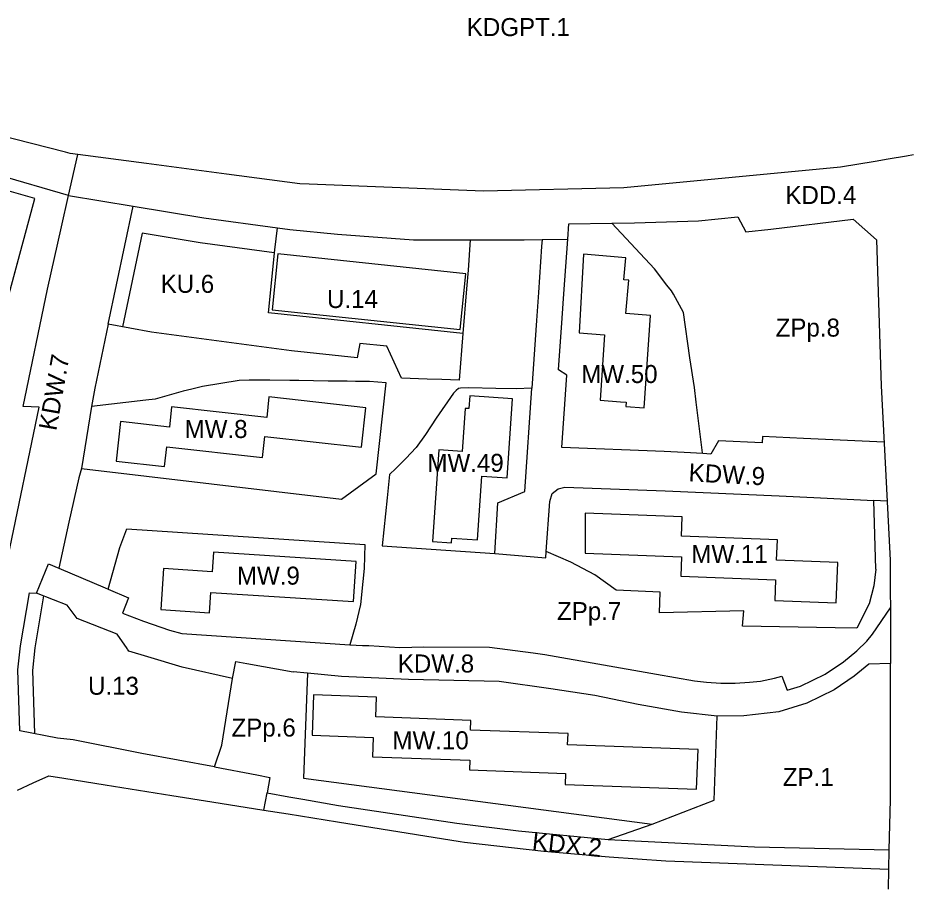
# Model space of a CAD drawing. Extents: x 7424434 to 7425898, y 5541432 to 5542659.
# Drawn here: x 7425170.3 to 7425417.1, y 5542089.1 to 5542330.8 of the extents above; entities that cross this region are included whole.
import ezdxf

# ---------------------------------------------------------------- set-up
doc = ezdxf.new("R2010")
doc.units = 0
for name, color, linetype in [('linie rozgraniczające', 7, 'Continuous'), ('nieprzekraczalne linie zabudowy', 7, 'Continuous'), ('obowiazujace linie zabudowy', 7, 'Continuous'), ('przeznaczenia terenów', 7, 'Continuous')]:
    doc.layers.add(name, color=color, linetype=linetype)

msp = doc.modelspace()

# ---------------------------------------------------------------- linework, layer by layer
at = {"layer": 'linie rozgraniczające'}
for p, q in [((7425183.57, 5542293.49), (7425160.74, 5542299.31)), ((7425184.89, 5542293.16), (7425183.57, 5542293.49)), ((7425187.01, 5542292.88), (7425184.89, 5542293.16)), ((7425184.45, 5542281.48), (7425148.18, 5542291.98)), ((7425184.45, 5542281.48), (7425187.01, 5542292.88)), ((7425206.02, 5542290.37), (7425187.01, 5542292.88)), ((7425408.2, 5542290.96), (7425398.58, 5542289.34)), ((7425411.81, 5542291.57), (7425408.2, 5542290.96)), ((7425416.94, 5542292.44), (7425411.81, 5542291.57)), ((7425418.88, 5542292.83), (7425416.94, 5542292.44)), ((7425175.09, 5542280.69), (7425147.13, 5542288.57)), ((7425228.29, 5542287.44), (7425206.02, 5542290.37)), ((7425398.58, 5542289.34), (7425338.51, 5542283.67)), ((7425248.56, 5542284.77), (7425228.29, 5542287.44)), ((7425251.22, 5542284.67), (7425248.56, 5542284.77)), ((7425299.51, 5542282.71), (7425251.22, 5542284.67)), ((7425338.51, 5542283.67), (7425299.51, 5542282.71)), ((7425162.36, 5542233.68), (7425175.09, 5542280.69)), ((7425182.51, 5542272.81), (7425184.45, 5542281.48)), ((7425184.45, 5542281.48), (7425202.31, 5542278.54)), ((7425195.46, 5542245.86), (7425202.31, 5542278.54)), ((7425202.31, 5542278.54), (7425221.99, 5542275.3)), ((7425221.99, 5542275.3), (7425242.43, 5542272.51)), ((7425322.91, 5542269.36), (7425323.21, 5542273.68)), ((7425323.21, 5542273.68), (7425335.12, 5542273.85)), ((7425335.12, 5542273.85), (7425341.48, 5542273.94)), ((7425346.97, 5542261.14), (7425335.12, 5542273.85)), ((7425341.48, 5542273.94), (7425359.22, 5542274.44)), ((7425359.22, 5542274.44), (7425370.12, 5542275.56)), ((7425370.12, 5542275.56), (7425372.37, 5542271.39)), ((7425379.27, 5542272.2), (7425402.12, 5542274.91)), ((7425402.12, 5542274.91), (7425408.57, 5542269.23)), ((7425178.62, 5542255.49), (7425182.51, 5542272.81)), ((7425241.69, 5542266.47), (7425242.43, 5542272.51)), ((7425242.43, 5542272.51), (7425245.84, 5542272.04)), ((7425245.84, 5542272.04), (7425259.08, 5542270.79)), ((7425259.08, 5542270.79), (7425280.15, 5542269.21)), ((7425372.37, 5542271.39), (7425379.27, 5542272.2)), ((7425280.15, 5542269.21), (7425295.81, 5542269.18)), ((7425295.81, 5542269.18), (7425295.25, 5542260.76)), ((7425295.81, 5542269.18), (7425310.79, 5542269.21)), ((7425310.79, 5542269.21), (7425315.8, 5542269.31)), ((7425315.8, 5542269.31), (7425315.67, 5542267.36)), ((7425315.8, 5542269.31), (7425322.91, 5542269.36)), ((7425321.86, 5542254.22), (7425322.91, 5542269.36)), ((7425408.57, 5542269.23), (7425409.91, 5542228.71)), ((7425239.87, 5542248.96), (7425241.69, 5542266.47)), ((7425315.67, 5542267.36), (7425314.8, 5542254.6)), ((7425350.41, 5542256.68), (7425346.97, 5542261.14)), ((7425295.25, 5542260.76), (7425294.84, 5542255.66)), ((7425351.68, 5542255.1), (7425350.41, 5542256.68)), ((7425171.81, 5542223), (7425178.62, 5542255.49)), ((7425294.84, 5542255.66), (7425293.83, 5542243.21)), ((7425314.8, 5542254.6), (7425314.27, 5542246.83)), ((7425321.4, 5542247.51), (7425321.86, 5542254.22)), ((7425352.22, 5542254.19), (7425351.68, 5542255.1)), ((7425355.05, 5542249.09), (7425352.22, 5542254.19)), ((7425293.83, 5542243.21), (7425239.87, 5542248.96)), ((7425356.82, 5542236.48), (7425355.05, 5542249.09)), ((7425314.27, 5542246.83), (7425313, 5542228.06)), ((7425320.35, 5542233.2), (7425321.4, 5542247.51)), ((7425195.46, 5542245.86), (7425191.73, 5542228.05)), ((7425207.44, 5542243.57), (7425195.46, 5542245.86)), ((7425246.3, 5542238.39), (7425207.44, 5542243.57)), ((7425293.83, 5542243.21), (7425292.77, 5542230.26)), ((7425265.25, 5542240.49), (7425264.54, 5542236.45)), ((7425272.74, 5542239.73), (7425265.25, 5542240.49)), ((7425276.84, 5542230.88), (7425272.74, 5542239.73)), ((7425264.54, 5542236.45), (7425246.3, 5542238.39)), ((7425358.08, 5542228.28), (7425356.82, 5542236.48)), ((7425322.66, 5542231.64), (7425320.35, 5542233.2)), ((7425321.3, 5542211.63), (7425322.66, 5542231.64)), ((7425231.73, 5542230.19), (7425221.58, 5542228.53)), ((7425234.56, 5542230.26), (7425231.73, 5542230.19)), ((7425240.3, 5542230.31), (7425234.56, 5542230.26)), ((7425245.85, 5542230.22), (7425240.3, 5542230.31)), ((7425248.36, 5542230.23), (7425245.85, 5542230.22)), ((7425256.47, 5542230.02), (7425248.36, 5542230.23)), ((7425260.5, 5542229.98), (7425256.47, 5542230.02)), ((7425261.68, 5542229.97), (7425260.5, 5542229.98)), ((7425264, 5542229.95), (7425261.68, 5542229.97)), ((7425267.93, 5542229.89), (7425264, 5542229.95)), ((7425272.56, 5542229.57), (7425267.93, 5542229.89)), ((7425269.75, 5542204.28), (7425272.56, 5542229.57)), ((7425283.94, 5542230.6), (7425276.84, 5542230.88)), ((7425288.03, 5542230.44), (7425283.94, 5542230.6)), ((7425292.77, 5542230.26), (7425288.03, 5542230.44)), ((7425191.73, 5542228.05), (7425190.81, 5542222.98)), ((7425216.2, 5542227.23), (7425208.46, 5542225.01)), ((7425218.66, 5542227.75), (7425216.2, 5542227.23)), ((7425221.58, 5542228.53), (7425218.66, 5542227.75)), ((7425291.22, 5542226.72), (7425286.45, 5542219.76)), ((7425291.93, 5542227.41), (7425291.22, 5542226.72)), ((7425292.61, 5542227.94), (7425291.93, 5542227.41)), ((7425293.16, 5542228.08), (7425292.61, 5542227.94)), ((7425295.47, 5542228.13), (7425293.16, 5542228.08)), ((7425302.93, 5542228.02), (7425295.47, 5542228.13)), ((7425308.61, 5542227.85), (7425302.93, 5542228.02)), ((7425313, 5542228.06), (7425308.61, 5542227.85)), ((7425311.05, 5542199.37), (7425313, 5542228.06)), ((7425358.59, 5542224.18), (7425358.08, 5542228.28)), ((7425409.91, 5542228.71), (7425410.74, 5542212.77)), ((7425205.89, 5542224.7), (7425190.81, 5542222.98)), ((7425208.46, 5542225.01), (7425205.89, 5542224.7)), ((7425360.33, 5542210.18), (7425358.59, 5542224.18)), ((7425167.64, 5542181.41), (7425176.32, 5542222.8)), ((7425176.32, 5542222.8), (7425171.81, 5542223)), ((7425190.81, 5542222.98), (7425188, 5542205.78)), ((7425286.45, 5542219.76), (7425283.44, 5542215.23)), ((7425283.44, 5542215.23), (7425280.85, 5542211.58)), ((7425376.96, 5542214.66), (7425376.86, 5542212.91)), ((7425388.36, 5542214.11), (7425376.96, 5542214.66)), ((7425410.72, 5542213.06), (7425388.36, 5542214.11)), ((7425280.85, 5542211.58), (7425278.01, 5542208.52)), ((7425349.63, 5542210.5), (7425321.3, 5542211.63)), ((7425364.71, 5542213.43), (7425362.61, 5542209.79)), ((7425376.86, 5542212.91), (7425364.71, 5542213.43)), ((7425410.74, 5542212.77), (7425411.12, 5542205.58)), ((7425355.24, 5542210.2), (7425349.63, 5542210.5)), ((7425360.36, 5542209.92), (7425355.24, 5542210.2)), ((7425360.36, 5542209.92), (7425360.33, 5542210.18)), ((7425362.61, 5542209.79), (7425360.36, 5542209.92)), ((7425278.01, 5542208.52), (7425275.19, 5542205.77)), ((7425188, 5542205.78), (7425187.26, 5542203.17)), ((7425188, 5542205.78), (7425260.12, 5542197.29)), ((7425260.12, 5542197.29), (7425269.75, 5542204.28)), ((7425273.44, 5542204.1), (7425272.83, 5542197.64)), ((7425275.19, 5542205.77), (7425273.44, 5542204.1)), ((7425411.12, 5542205.58), (7425412.39, 5542180.33)), ((7425187.26, 5542203.17), (7425184.55, 5542190.91)), ((7425303.52, 5542196.3), (7425311.05, 5542199.37)), ((7425318.64, 5542198.82), (7425320.24, 5542200.19)), ((7425320.24, 5542200.19), (7425322.14, 5542200.62)), ((7425322.14, 5542200.62), (7425349.93, 5542199.61)), ((7425349.93, 5542199.61), (7425381.55, 5542198.2)), ((7425272.83, 5542197.64), (7425271.48, 5542184.34)), ((7425316.92, 5542182.74), (7425317.93, 5542196.67)), ((7425317.93, 5542196.67), (7425318.64, 5542198.82)), ((7425381.55, 5542198.2), (7425391.21, 5542197.73)), ((7425391.21, 5542197.73), (7425407.82, 5542196.91)), ((7425408.42, 5542177.86), (7425407.82, 5542196.91)), ((7425411.56, 5542196.73), (7425407.82, 5542196.91)), ((7425302.72, 5542182.24), (7425303.52, 5542196.3)), ((7425184.55, 5542190.91), (7425181.72, 5542178.11)), ((7425198.67, 5542183.86), (7425200.6, 5542189.1)), ((7425200.6, 5542189.1), (7425266.62, 5542184.67)), ((7425266.62, 5542184.67), (7425266.4, 5542178.02)), ((7425271.48, 5542184.34), (7425302.72, 5542182.24)), ((7425195.42, 5542172.35), (7425198.67, 5542183.86)), ((7425302.72, 5542182.24), (7425316.87, 5542180.98)), ((7425316.87, 5542180.98), (7425316.92, 5542182.74)), ((7425323.79, 5542179.83), (7425316.92, 5542182.74)), ((7425330.44, 5542176.29), (7425323.79, 5542179.83)), ((7425412.39, 5542180.33), (7425412.47, 5542158.39)), ((7425175.56, 5542171.19), (7425178.82, 5542179.33)), ((7425178.82, 5542179.33), (7425181.72, 5542178.11)), ((7425181.72, 5542178.11), (7425194.59, 5542172.7)), ((7425266.4, 5542178.02), (7425266.09, 5542174.46)), ((7425408.42, 5542177.86), (7425407.83, 5542173.21)), ((7425266.09, 5542174.46), (7425265.47, 5542168.11)), ((7425336.37, 5542172.09), (7425330.44, 5542176.29)), ((7425194.59, 5542172.7), (7425195.42, 5542172.35)), ((7425195.42, 5542172.35), (7425201.05, 5542169.91)), ((7425348.56, 5542171.53), (7425336.37, 5542172.09)), ((7425407.83, 5542173.21), (7425406.55, 5542168.22)), ((7425171.12, 5542156.57), (7425173.61, 5542171.33)), ((7425173.61, 5542171.33), (7425175.56, 5542171.19)), ((7425180.23, 5542169.39), (7425175.56, 5542171.19)), ((7425201.05, 5542169.91), (7425199.4, 5542165.66)), ((7425348.37, 5542165.75), (7425348.56, 5542171.53)), ((7425184.08, 5542167.86), (7425180.23, 5542169.39)), ((7425186.82, 5542164.23), (7425184.08, 5542167.86)), ((7425265.47, 5542168.11), (7425264.1, 5542162.58)), ((7425406.55, 5542168.22), (7425403.08, 5542161.53)), ((7425407.49, 5542159.86), (7425412.44, 5542167.14)), ((7425199.4, 5542165.66), (7425205.25, 5542163.44)), ((7425371.77, 5542166.31), (7425348.37, 5542165.75)), ((7425371.38, 5542162.06), (7425371.77, 5542166.31)), ((7425197.92, 5542159.82), (7425186.82, 5542164.23)), ((7425205.25, 5542163.44), (7425212.45, 5542160.99)), ((7425264.1, 5542162.58), (7425262.48, 5542156.86)), ((7425200.65, 5542155.88), (7425197.92, 5542159.82)), ((7425212.45, 5542160.99), (7425215.83, 5542160.01)), ((7425215.83, 5542160.01), (7425262.48, 5542156.86)), ((7425397.14, 5542161.63), (7425371.38, 5542162.06)), ((7425403.08, 5542161.53), (7425397.14, 5542161.63)), ((7425405.93, 5542157.93), (7425407.49, 5542159.86)), ((7425403.16, 5542155.23), (7425405.93, 5542157.93)), ((7425412.47, 5542158.39), (7425412.47, 5542151.68)), ((7425170.4, 5542149.94), (7425171.12, 5542156.57)), ((7425200.8, 5542155.68), (7425200.65, 5542155.88)), ((7425201.15, 5542155.17), (7425200.8, 5542155.68)), ((7425206.47, 5542153.56), (7425201.15, 5542155.17)), ((7425262.48, 5542156.86), (7425265.97, 5542156.69)), ((7425265.97, 5542156.69), (7425267.71, 5542156.66)), ((7425267.71, 5542156.66), (7425276.37, 5542156.15)), ((7425276.37, 5542156.15), (7425283.01, 5542156.29)), ((7425283.01, 5542156.29), (7425301.2, 5542156.23)), ((7425301.2, 5542156.23), (7425313.36, 5542154.65)), ((7425399.42, 5542152.19), (7425403.16, 5542155.23)), ((7425215.96, 5542150.65), (7425206.47, 5542153.56)), ((7425229.91, 5542147.54), (7425230.88, 5542152.26)), ((7425230.88, 5542152.26), (7425233.88, 5542151.69)), ((7425313.36, 5542154.65), (7425316.55, 5542154.19)), ((7425316.55, 5542154.19), (7425347.51, 5542148.79)), ((7425170.94, 5542133.08), (7425170.4, 5542149.94)), ((7425229.91, 5542147.54), (7425215.96, 5542150.65)), ((7425233.88, 5542151.69), (7425246.78, 5542149.37)), ((7425394.32, 5542148.72), (7425399.42, 5542152.19)), ((7425406.49, 5542151.49), (7425402.41, 5542148.18)), ((7425412.47, 5542151.68), (7425406.49, 5542151.49)), ((7425412.45, 5542113.88), (7425412.47, 5542151.68)), ((7425226.99, 5542129.1), (7425229.91, 5542147.54)), ((7425250.73, 5542149.01), (7425246.78, 5542149.37)), ((7425250.73, 5542149), (7425249.63, 5542119.88)), ((7425250.73, 5542149), (7425250.73, 5542149.01)), ((7425260.12, 5542148.11), (7425250.73, 5542149)), ((7425278.73, 5542147.23), (7425260.12, 5542148.11)), ((7425347.51, 5542148.79), (7425358.05, 5542146.93)), ((7425376.39, 5542146.83), (7425380.31, 5542147.65)), ((7425380.31, 5542147.65), (7425382.33, 5542148.16)), ((7425382.33, 5542148.16), (7425383.84, 5542144.31)), ((7425387.46, 5542145.42), (7425394.32, 5542148.72)), ((7425402.41, 5542148.18), (7425396.83, 5542144.38)), ((7425303.91, 5542146.68), (7425278.73, 5542147.23)), ((7425318.27, 5542144.71), (7425303.91, 5542146.68)), ((7425358.05, 5542146.93), (7425361.38, 5542146.51)), ((7425361.38, 5542146.51), (7425365.37, 5542146.28)), ((7425365.37, 5542146.28), (7425369.38, 5542146.3)), ((7425369.38, 5542146.3), (7425373.38, 5542146.53)), ((7425373.38, 5542146.53), (7425376.39, 5542146.83)), ((7425383.84, 5542144.31), (7425387.46, 5542145.42)), ((7425330.41, 5542142.79), (7425318.27, 5542144.71)), ((7425342.45, 5542140.35), (7425330.41, 5542142.79)), ((7425396.83, 5542144.38), (7425389.29, 5542140.75)), ((7425354.46, 5542138.22), (7425342.45, 5542140.35)), ((7425389.29, 5542140.75), (7425381.44, 5542138.35)), ((7425364.36, 5542137.06), (7425354.46, 5542138.22)), ((7425381.44, 5542138.35), (7425371.8, 5542137.18)), ((7425363.51, 5542113.82), (7425364.36, 5542137.06)), ((7425371.8, 5542137.18), (7425364.36, 5542137.06)), ((7425181.39, 5542131.02), (7425170.94, 5542133.08)), ((7425185.67, 5542130.55), (7425181.39, 5542131.02)), ((7425204.79, 5542126.76), (7425185.67, 5542130.55)), ((7425224.91, 5542123.04), (7425226.99, 5542129.1)), ((7425224.91, 5542123.04), (7425204.79, 5542126.76)), ((7425224.91, 5542123.04), (7425236.63, 5542120.82)), ((7425174.64, 5542118.61), (7425178.99, 5542120.59)), ((7425178.99, 5542120.59), (7425183.1, 5542119.93)), ((7425236.63, 5542120.82), (7425240.31, 5542120.12)), ((7425170.29, 5542116.62), (7425174.64, 5542118.61)), ((7425183.1, 5542119.93), (7425194.6, 5542118.09)), ((7425194.6, 5542118.09), (7425213.07, 5542115.13)), ((7425240.31, 5542120.12), (7425239.5, 5542115.8)), ((7425249.63, 5542119.88), (7425346.33, 5542107.11)), ((7425238.61, 5542111.05), (7425239.5, 5542115.8)), ((7425239.5, 5542115.8), (7425245.53, 5542114.73)), ((7425213.07, 5542115.13), (7425224.14, 5542113.36)), ((7425224.14, 5542113.36), (7425238.61, 5542111.05)), ((7425245.53, 5542114.73), (7425249.41, 5542114.04)), ((7425249.41, 5542114.04), (7425259.28, 5542112.28)), ((7425346.33, 5542107.11), (7425363.51, 5542113.82)), ((7425412.12, 5542100.01), (7425412.45, 5542113.88)), ((7425238.61, 5542111.05), (7425245.35, 5542109.97)), ((7425259.28, 5542112.28), (7425292.12, 5542107.43)), ((7425245.35, 5542109.97), (7425259, 5542107.78)), ((7425259, 5542107.78), (7425293.08, 5542102.32)), ((7425292.12, 5542107.43), (7425309.28, 5542105.3)), ((7425334.14, 5542102.85), (7425346.33, 5542107.11)), ((7425309.28, 5542105.3), (7425334.14, 5542102.85)), ((7425293.08, 5542102.32), (7425294.24, 5542102.17)), ((7425294.24, 5542102.17), (7425316.28, 5542099.68)), ((7425334.14, 5542102.85), (7425374.69, 5542100.88)), ((7425374.69, 5542100.88), (7425412.12, 5542100.01)), ((7425316.28, 5542099.68), (7425334.37, 5542098.12)), ((7425334.37, 5542098.12), (7425350.12, 5542097)), ((7425412, 5542094.65), (7425412.12, 5542100.01)), ((7425350.12, 5542097), (7425412, 5542094.65)), ((7425411.87, 5542089.11), (7425412, 5542094.65))]:
    msp.add_line(p, q, dxfattribs=at)
at = {"layer": 'nieprzekraczalne linie zabudowy'}
for points in [[(7425241.48, 5542265.57), (7425220.95, 5542268.38), (7425204.82, 5542271.03), (7425199.37, 5542245.04)], [(7425177.52, 5542170.44), (7425175.08, 5542156.02), (7425174.41, 5542149.79), (7425174.97, 5542132.26)]]:
    msp.add_lwpolyline(points, dxfattribs=at)
at = {"layer": 'obowiazujace linie zabudowy'}
for points in [[(7425240.89, 5542249.84), (7425293.06, 5542244.33), (7425294.69, 5542259.75), (7425242.52, 5542265.36)], [(7425327.25, 5542265.26), (7425326.06, 5542243.39), (7425333.13, 5542242.91), (7425331.89, 5542224.7), (7425337.55, 5542224.32), (7425339.09, 5542224.22), (7425339.01, 5542223), (7425344.16, 5542222.65), (7425345.89, 5542248.2), (7425339.04, 5542248.8), (7425339.84, 5542258.01), (7425338.52, 5542258.13), (7425339.05, 5542264.23)], [(7425240.03, 5542225.65), (7425239.4, 5542219.98), (7425213.03, 5542222.92), (7425212.4, 5542217.28), (7425198.85, 5542218.8), (7425197.62, 5542207.81), (7425211.06, 5542206.31), (7425211.68, 5542211.83), (7425238.23, 5542208.87), (7425238.87, 5542214.68), (7425265.68, 5542211.69), (7425266.9, 5542222.64)], [(7425307.57, 5542225.12), (7425295.72, 5542225.91), (7425295.48, 5542222.39), (7425294.45, 5542222.46), (7425293.66, 5542210.55), (7425287.13, 5542210.98), (7425285.44, 5542185.57), (7425290.66, 5542185.22), (7425290.74, 5542186.46), (7425292.14, 5542186.37), (7425297.89, 5542185.98), (7425299.06, 5542203.63), (7425306.11, 5542203.16)], [(7425327.74, 5542193.4), (7425327.73, 5542182.28), (7425354.48, 5542181.33), (7425354.27, 5542175.9), (7425380.59, 5542174.88), (7425380.37, 5542169.2), (7425397.4, 5542168.54), (7425397.84, 5542179.73), (7425380.87, 5542180.39), (7425381.09, 5542186.01), (7425354.48, 5542187.05), (7425354.69, 5542192.35)], [(7425224.63, 5542182.6), (7425224.28, 5542177.14), (7425210.73, 5542178.02), (7425209.99, 5542166.67), (7425223.57, 5542165.79), (7425223.94, 5542171.44), (7425263.46, 5542168.87), (7425264.19, 5542180.02)], [(7425252.42, 5542143.01), (7425252, 5542131.79), (7425268.98, 5542131.17), (7425268.79, 5542125.86), (7425295.72, 5542124.86), (7425295.62, 5542122.21), (7425322.34, 5542121.23), (7425322.23, 5542118.18), (7425358.66, 5542116.83), (7425359.07, 5542127.85), (7425322.88, 5542129.19), (7425323, 5542132.25), (7425295.97, 5542133.25), (7425296.07, 5542135.92), (7425269.66, 5542136.89), (7425269.87, 5542142.36)]]:
    msp.add_lwpolyline(points, close=True, dxfattribs=at)

# ---------------------------------------------------------------- texts
at = {"layer": 'przeznaczenia terenów'}
for s, p in [('KDGPT.1', (7425294.91, 5542325.72)), ('KDD.4', (7425383.3, 5542279.13)), ('KU.6', (7425209.97, 5542254.51)), ('U.14', (7425256.13, 5542250.3)), ('ZPp.8', (7425380.6, 5542242.37)), ('MW.50', (7425326.67, 5542229.5)), ('MW.8', (7425216.62, 5542214.25)), ('MW.49', (7425283.99, 5542204.86)), ('MW.11', (7425357.22, 5542179.57)), ('MW.9', (7425231.14, 5542173.58)), ('ZPp.7', (7425319.94, 5542163.73)), ('KDW.8', (7425275.77, 5542149.21)), ('U.13', (7425189.83, 5542143.04)), ('ZPp.6', (7425229.63, 5542131.44)), ('MW.10', (7425274.28, 5542127.91)), ('ZP.1', (7425382.58, 5542117.74))]:
    msp.add_text(s, height=5, dxfattribs=at).set_placement(p)
for s, rotation, p in [('KDW.7', 80, (7425181.02, 5542216.07)), ('KDW.9', 356.9268, (7425356.36, 5542202.24)), ('KDX.2', 353.8307, (7425312.85, 5542100.07))]:
    msp.add_text(s, height=5, rotation=rotation, dxfattribs=at).set_placement(p)

doc.saveas('drawing.dxf')
